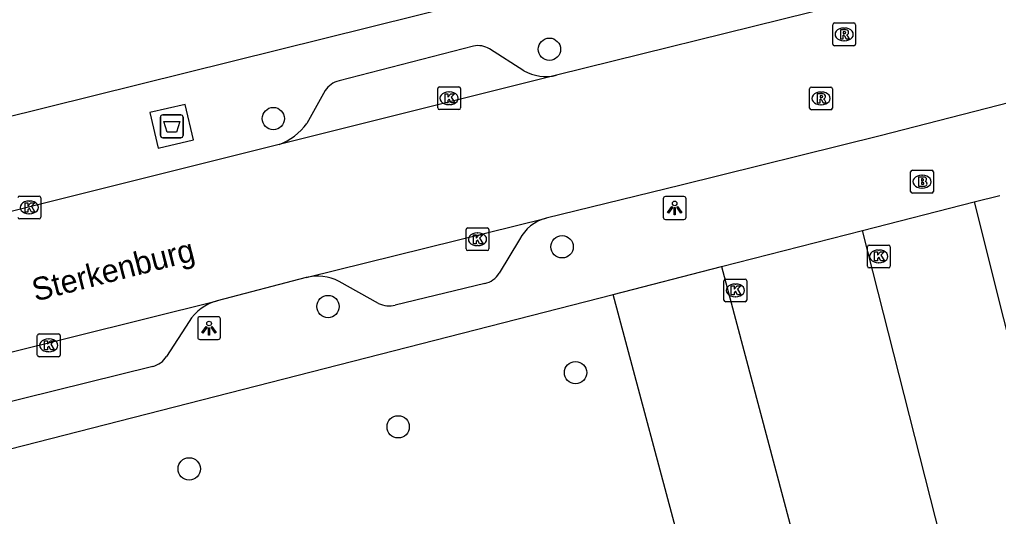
# Model space of a CAD drawing. Extents: x 157793 to 159380, y 380882 to 382313.
# Drawn here: x 158565.92 to 158608.83, y 381261.79 to 381283.58 of the extents above; entities that cross this region are included whole.
import ezdxf

# ---------------------------------------------------------------- set-up
doc = ezdxf.new("R2010")
doc.units = 0
for name, color, linetype in [('IMGEO_Afval_apart_plaats', 7, 'Continuous'), ('IMGEO_Boom', 7, 'Continuous'), ('IMGEO_Brandkraan', 7, 'Continuous'), ('IMGEO_Kolk', 7, 'Continuous'), ('IMGEO_Lichtpunt', 7, 'Continuous'), ('IMGEO_Openbare_ruimte_label', 7, 'Continuous'), ('IMGEO_Parkeervlak_open', 7, 'Continuous'), ('IMGEO_Rijbaan_lokaal_gesloten', 7, 'Continuous'), ('IMGEO_Rijbaan_lokaal_open', 7, 'Continuous'), ('IMGEO_Rioolput', 7, 'Continuous'), ('IMGEO_Voetpad_gesloten', 7, 'Continuous'), ('IMGEO_Voetpad_open', 7, 'Continuous')]:
    doc.layers.add(name, color=color, linetype=linetype)

msp = doc.modelspace()

# ---------------------------------------------------------------- linework, layer by layer
at = {"layer": 'IMGEO_Afval_apart_plaats'}
for p, q in [((158572.097, 381278.498), (158572.097, 381279.298)), ((158572.097, 381279.298), (158572.097, 381278.498)), ((158572.197, 381279.398), (158572.987, 381279.398)), ((158572.987, 381279.398), (158572.197, 381279.398)), ((158573.087, 381279.298), (158573.087, 381278.498)), ((158573.087, 381278.498), (158573.087, 381279.298)), ((158572.987, 381278.398), (158572.197, 381278.398)), ((158572.197, 381278.398), (158572.987, 381278.398))]:
    msp.add_line(p, q, dxfattribs=at)
msp.add_lwpolyline([(158572.24, 381279.112), (158572.944, 381279.112), (158572.795, 381278.642), (158572.389, 381278.642), (158572.24, 381279.112)], dxfattribs=at)
for centre, start, end in [((158572.197, 381279.298), 90, 180), ((158572.197, 381279.298), 90, 180), ((158572.987, 381279.298), 0, 90), ((158572.987, 381279.298), 360, 90), ((158572.197, 381278.498), 180, 270), ((158572.197, 381278.498), 180, 270), ((158572.987, 381278.498), 270, 0), ((158572.987, 381278.498), 270, 0)]:
    msp.add_arc(centre, 0.1, start, end, dxfattribs=at)
at = {"layer": 'IMGEO_Boom'}
for centre in [(158589.147, 381282.275), (158577.046, 381279.235), (158589.702, 381273.613), (158579.443, 381270.995), (158590.291, 381268.096), (158582.517, 381265.72), (158573.359, 381263.875)]:
    msp.add_circle(centre, 0.489, dxfattribs=at)
at = {"layer": 'IMGEO_Brandkraan'}
for p, q in [((158604.979, 381276.043), (158604.979, 381276.895)), ((158605.054, 381276.969), (158605.906, 381276.969)), ((158605.467, 381276.749), (158605.492, 381276.749)), ((158605.98, 381276.895), (158605.98, 381276.043)), ((158605.49, 381276.189), (158605.465, 381276.189)), ((158605.906, 381275.969), (158605.054, 381275.969))]:
    msp.add_line(p, q, dxfattribs=at)
for points in [[(158604.979, 381276.043), (158604.979, 381276.895)], [(158605.054, 381276.969), (158605.906, 381276.969)], [(158605.327, 381276.669), (158605.327, 381276.269), (158605.54, 381276.269)], [(158605.558, 381276.669), (158605.327, 381276.669)], [(158605.506, 381276.588), (158605.452, 381276.588), (158605.452, 381276.512)], [(158605.98, 381276.895), (158605.98, 381276.043)], [(158605.452, 381276.512), (158605.505, 381276.512)], [(158605.514, 381276.436), (158605.452, 381276.436), (158605.452, 381276.355)], [(158605.452, 381276.355), (158605.514, 381276.355)], [(158605.906, 381275.969), (158605.054, 381275.969)]]:
    msp.add_lwpolyline(points, dxfattribs=at)
for centre, radius, start, end in [((158605.056, 381276.893), 0.0765, 91.552, 178.448), ((158605.056, 381276.893), 0.0765, 91.552, 178.448), ((158605.507, 381276.55), 0.0379, 267.8285, 90.9355), ((158605.562, 381276.524), 0.145, 59.4692, 91.5367), ((158605.587, 381276.571), 0.0922, 285.5137, 58.1501), ((158605.904, 381276.893), 0.0765, 1.552, 88.448), ((158605.904, 381276.893), 0.0765, 1.552, 88.448), ((158605.515, 381276.395), 0.0404, 269.8759, 90.5077), ((158605.546, 381276.52), 0.251, 268.6676, 293.5347), ((158605.592, 381276.379), 0.105, 301.3115, 78.989), ((158605.056, 381276.045), 0.0765, 181.552, 268.448), ((158605.056, 381276.045), 0.0765, 181.552, 268.448), ((158605.904, 381276.045), 0.0765, 271.552, 358.448), ((158605.904, 381276.045), 0.0765, 271.552, 358.448)]:
    msp.add_arc(centre, radius, start, end, dxfattribs=at)
for centre, major_axis, ratio, start_param, end_param in [((158605.466, 381276.469), (-0.387, 0.002), 0.722429, 4.712389, 7.853982), ((158605.491, 381276.469), (-0.39, 0.002), 0.717154, 1.570796, 4.712389)]:
    msp.add_ellipse(centre, major_axis=major_axis, ratio=ratio, start_param=start_param, end_param=end_param, dxfattribs=at)
at = {"layer": 'IMGEO_Kolk'}
for p, q in [((158584.25, 381279.701), (158584.25, 381280.553)), ((158584.325, 381280.627), (158585.177, 381280.627)), ((158585.251, 381280.553), (158585.251, 381279.701)), ((158584.738, 381280.407), (158584.763, 381280.407)), ((158585.177, 381279.627), (158584.325, 381279.627)), ((158584.761, 381279.847), (158584.736, 381279.847)), ((158565.924, 381275.839), (158566.776, 381275.839)), ((158566.85, 381275.765), (158566.85, 381274.913)), ((158566.337, 381275.619), (158566.362, 381275.619)), ((158566.36, 381275.059), (158566.335, 381275.059)), ((158566.776, 381274.839), (158565.924, 381274.839)), ((158585.569, 381274.445), (158586.421, 381274.445)), ((158585.494, 381273.519), (158585.494, 381274.371)), ((158585.982, 381274.225), (158586.007, 381274.225)), ((158586.495, 381274.371), (158586.495, 381273.519)), ((158586.005, 381273.665), (158585.98, 381273.665)), ((158603.081, 381272.765), (158603.081, 381273.617)), ((158603.156, 381273.691), (158604.008, 381273.691)), ((158604.082, 381273.617), (158604.082, 381272.765)), ((158586.421, 381273.445), (158585.569, 381273.445)), ((158603.569, 381273.471), (158603.594, 381273.471)), ((158603.592, 381272.911), (158603.567, 381272.911)), ((158604.008, 381272.691), (158603.156, 381272.691)), ((158596.797, 381271.275), (158596.797, 381272.127)), ((158596.872, 381272.201), (158597.724, 381272.201)), ((158597.285, 381271.981), (158597.31, 381271.981)), ((158597.798, 381272.127), (158597.798, 381271.275)), ((158597.308, 381271.421), (158597.283, 381271.421)), ((158597.724, 381271.201), (158596.872, 381271.201)), ((158566.702, 381268.869), (158566.702, 381269.721)), ((158566.777, 381269.795), (158567.629, 381269.795)), ((158567.703, 381269.721), (158567.703, 381268.869)), ((158567.19, 381269.575), (158567.215, 381269.575)), ((158567.213, 381269.015), (158567.188, 381269.015)), ((158567.629, 381268.795), (158566.777, 381268.795))]:
    msp.add_line(p, q, dxfattribs=at)
for points in [[(158584.25, 381279.701), (158584.25, 381280.553)], [(158584.325, 381280.627), (158585.177, 381280.627)], [(158585.251, 381280.553), (158585.251, 381279.701)], [(158584.571, 381280.327), (158584.694, 381280.327), (158584.694, 381280.176), (158584.824, 381280.327), (158584.988, 381280.327), (158584.842, 381280.176), (158584.995, 381279.927), (158584.843, 381279.927), (158584.758, 381280.091), (158584.694, 381280.024), (158584.694, 381279.927), (158584.571, 381279.927), (158584.571, 381280.327)], [(158585.177, 381279.627), (158584.325, 381279.627)], [(158565.924, 381275.839), (158566.776, 381275.839)], [(158566.85, 381275.765), (158566.85, 381274.913)], [(158566.17, 381275.539), (158566.293, 381275.539), (158566.293, 381275.388), (158566.423, 381275.539), (158566.587, 381275.539), (158566.441, 381275.388), (158566.594, 381275.139), (158566.442, 381275.139), (158566.357, 381275.303), (158566.293, 381275.236), (158566.293, 381275.139), (158566.17, 381275.139), (158566.17, 381275.539)], [(158566.776, 381274.839), (158565.924, 381274.839)], [(158585.569, 381274.445), (158586.421, 381274.445)], [(158585.494, 381273.519), (158585.494, 381274.371)], [(158585.815, 381274.145), (158585.938, 381274.145), (158585.938, 381273.994), (158586.068, 381274.145), (158586.232, 381274.145), (158586.086, 381273.994), (158586.239, 381273.745), (158586.087, 381273.745), (158586.002, 381273.909), (158585.938, 381273.842), (158585.938, 381273.745), (158585.815, 381273.745), (158585.815, 381274.145)], [(158586.495, 381274.371), (158586.495, 381273.519)], [(158603.081, 381272.765), (158603.081, 381273.617)], [(158603.156, 381273.691), (158604.008, 381273.691)], [(158604.082, 381273.617), (158604.082, 381272.765)], [(158586.421, 381273.445), (158585.569, 381273.445)], [(158603.402, 381273.391), (158603.525, 381273.391), (158603.525, 381273.24), (158603.655, 381273.391), (158603.819, 381273.391), (158603.673, 381273.24), (158603.826, 381272.991), (158603.674, 381272.991), (158603.589, 381273.155), (158603.525, 381273.088), (158603.525, 381272.991), (158603.402, 381272.991), (158603.402, 381273.391)], [(158604.008, 381272.691), (158603.156, 381272.691)], [(158596.797, 381271.275), (158596.797, 381272.127)], [(158596.872, 381272.201), (158597.724, 381272.201)], [(158597.118, 381271.901), (158597.241, 381271.901), (158597.241, 381271.75), (158597.371, 381271.901), (158597.535, 381271.901), (158597.389, 381271.75), (158597.542, 381271.501), (158597.39, 381271.501), (158597.305, 381271.665), (158597.241, 381271.598), (158597.241, 381271.501), (158597.118, 381271.501), (158597.118, 381271.901)], [(158597.798, 381272.127), (158597.798, 381271.275)], [(158597.724, 381271.201), (158596.872, 381271.201)], [(158566.702, 381268.869), (158566.702, 381269.721)], [(158566.777, 381269.795), (158567.629, 381269.795)], [(158567.703, 381269.721), (158567.703, 381268.869)], [(158567.023, 381269.495), (158567.146, 381269.495), (158567.146, 381269.344), (158567.276, 381269.495), (158567.44, 381269.495), (158567.294, 381269.344), (158567.447, 381269.095), (158567.295, 381269.095), (158567.21, 381269.259), (158567.146, 381269.192), (158567.146, 381269.095), (158567.023, 381269.095), (158567.023, 381269.495)], [(158567.629, 381268.795), (158566.777, 381268.795)]]:
    msp.add_lwpolyline(points, dxfattribs=at)
for centre, start, end in [((158584.327, 381280.551), 91.552, 178.448), ((158584.327, 381280.551), 91.552, 178.448), ((158585.175, 381280.551), 1.552, 88.448), ((158585.175, 381280.551), 1.552, 88.448), ((158584.327, 381279.703), 181.552, 268.448), ((158584.327, 381279.703), 181.552, 268.448), ((158585.175, 381279.703), 271.552, 358.448), ((158585.175, 381279.703), 271.552, 358.448), ((158565.926, 381275.763), 91.552, 178.448), ((158565.926, 381275.763), 91.552, 178.448), ((158566.774, 381275.763), 1.552, 88.448), ((158566.774, 381275.763), 1.552, 88.448), ((158565.926, 381274.915), 181.552, 268.448), ((158565.926, 381274.915), 181.552, 268.448), ((158566.774, 381274.915), 271.552, 358.448), ((158566.774, 381274.915), 271.552, 358.448), ((158585.571, 381274.369), 91.552, 178.448), ((158585.571, 381274.369), 91.552, 178.448), ((158586.419, 381274.369), 1.552, 88.448), ((158586.419, 381274.369), 1.552, 88.448), ((158603.158, 381273.615), 91.552, 178.448), ((158603.158, 381273.615), 91.552, 178.448), ((158604.006, 381273.615), 1.552, 88.448), ((158604.006, 381273.615), 1.552, 88.448), ((158585.571, 381273.521), 181.552, 268.448), ((158585.571, 381273.521), 181.552, 268.448), ((158586.419, 381273.521), 271.552, 358.448), ((158586.419, 381273.521), 271.552, 358.448), ((158603.158, 381272.767), 181.552, 268.448), ((158603.158, 381272.767), 181.552, 268.448), ((158604.006, 381272.767), 271.552, 358.448), ((158604.006, 381272.767), 271.552, 358.448), ((158596.874, 381272.125), 91.552, 178.448), ((158596.874, 381272.125), 91.552, 178.448), ((158597.722, 381272.125), 1.552, 88.448), ((158597.722, 381272.125), 1.552, 88.448), ((158596.874, 381271.277), 181.552, 268.448), ((158596.874, 381271.277), 181.552, 268.448), ((158597.722, 381271.277), 271.552, 358.448), ((158597.722, 381271.277), 271.552, 358.448), ((158566.779, 381269.719), 91.552, 178.448), ((158566.779, 381269.719), 91.552, 178.448), ((158567.627, 381269.719), 1.552, 88.448), ((158567.627, 381269.719), 1.552, 88.448), ((158566.779, 381268.871), 181.552, 268.448), ((158566.779, 381268.871), 181.552, 268.448), ((158567.627, 381268.871), 271.552, 358.448), ((158567.627, 381268.871), 271.552, 358.448)]:
    msp.add_arc(centre, 0.0765, start, end, dxfattribs=at)
for centre, major_axis, ratio, start_param, end_param in [((158584.737, 381280.127), (-0.387, 0.002), 0.722429, 4.712389, 7.853982), ((158584.762, 381280.127), (-0.39, 0.002), 0.717154, 1.570796, 4.712389), ((158566.336, 381275.339), (-0.387, 0.002), 0.722429, 4.712389, 7.853982), ((158566.361, 381275.339), (-0.39, 0.002), 0.717154, 1.570796, 4.712389), ((158585.981, 381273.945), (-0.387, 0.002), 0.722429, 4.712389, 7.853982), ((158586.006, 381273.945), (-0.39, 0.002), 0.717154, 1.570796, 4.712389), ((158603.568, 381273.191), (-0.387, 0.002), 0.722429, 4.712389, 7.853982), ((158603.593, 381273.191), (-0.39, 0.002), 0.717154, 1.570796, 4.712389), ((158597.284, 381271.701), (-0.387, 0.002), 0.722429, 4.712389, 7.853982), ((158597.309, 381271.701), (-0.39, 0.002), 0.717154, 1.570796, 4.712389), ((158567.189, 381269.295), (-0.387, 0.002), 0.722429, 4.712389, 7.853982), ((158567.214, 381269.295), (-0.39, 0.002), 0.717154, 1.570796, 4.712389)]:
    msp.add_ellipse(centre, major_axis=major_axis, ratio=ratio, start_param=start_param, end_param=end_param, dxfattribs=at)
at = {"layer": 'IMGEO_Lichtpunt'}
for p, q in [((158594.139, 381275.718), (158594.139, 381274.911)), ((158594.139, 381275.718), (158594.139, 381274.911)), ((158595.041, 381275.813), (158594.233, 381275.813)), ((158595.041, 381275.813), (158594.233, 381275.813)), ((158595.135, 381274.911), (158595.135, 381275.718)), ((158595.135, 381274.911), (158595.135, 381275.718)), ((158594.233, 381274.817), (158595.041, 381274.817)), ((158594.233, 381274.817), (158595.041, 381274.817)), ((158573.731, 381270.451), (158573.731, 381269.644)), ((158573.731, 381270.451), (158573.731, 381269.644)), ((158574.633, 381270.546), (158573.825, 381270.546)), ((158574.633, 381270.546), (158573.825, 381270.546)), ((158574.727, 381269.644), (158574.727, 381270.451)), ((158574.727, 381269.644), (158574.727, 381270.451)), ((158573.825, 381269.55), (158574.633, 381269.55)), ((158573.825, 381269.55), (158574.633, 381269.55))]:
    msp.add_line(p, q, dxfattribs=at)
for points in [[(158594.513, 381275.382), (158594.552, 381275.354), (158594.364, 381275.092), (158594.326, 381275.119), (158594.513, 381275.382)], [(158594.615, 381275.334), (158594.662, 381275.334), (158594.662, 381275.012), (158594.615, 381275.012), (158594.615, 381275.334)], [(158594.725, 381275.354), (158594.763, 381275.381), (158594.95, 381275.119), (158594.911, 381275.091), (158594.725, 381275.354)], [(158574.105, 381270.115), (158574.144, 381270.087), (158573.956, 381269.825), (158573.918, 381269.852), (158574.105, 381270.115)], [(158574.207, 381270.067), (158574.254, 381270.067), (158574.254, 381269.745), (158574.207, 381269.745), (158574.207, 381270.067)], [(158574.317, 381270.087), (158574.355, 381270.114), (158574.542, 381269.852), (158574.503, 381269.824), (158574.317, 381270.087)]]:
    msp.add_lwpolyline(points, dxfattribs=at)
for centre in [(158594.638, 381275.516), (158574.23, 381270.249)]:
    msp.add_circle(centre, 0.0994, dxfattribs=at)
for centre, start, end in [((158594.233, 381275.718), 90, 180), ((158594.233, 381275.718), 90, 180), ((158595.041, 381275.718), 0, 90), ((158595.041, 381275.718), 0, 90), ((158594.233, 381274.911), 180, 270), ((158594.233, 381274.911), 180, 270), ((158595.041, 381274.911), 270, 0), ((158595.041, 381274.911), 270, 360), ((158573.825, 381270.451), 90, 180), ((158573.825, 381270.451), 90, 180), ((158574.633, 381270.451), 0, 90), ((158574.633, 381270.451), 0, 90), ((158573.825, 381269.644), 180, 270), ((158573.825, 381269.644), 180, 270), ((158574.633, 381269.644), 270, 0), ((158574.633, 381269.644), 270, 360)]:
    msp.add_arc(centre, 0.0946, start, end, dxfattribs=at)
at = {"layer": 'IMGEO_Parkeervlak_open'}
msp.add_lwpolyline([(158595.165, 381259.444), (158591.941, 381271.524)], dxfattribs=at)
at = {"layer": 'IMGEO_Rijbaan_lokaal_gesloten'}
for points in [[(158609.469, 381286.151), (158607.008, 381285.513), (158600.58, 381283.887), (158589.462, 381281.136)], [(158589.462, 381281.136), (158577.301, 381278.092)], [(158610.86, 381280.329), (158603.643, 381278.485), (158594.916, 381276.32), (158588.997, 381274.872)], [(158577.301, 381278.092), (158564.14, 381274.813), (158563.943, 381274.765)], [(158578.484, 381272.266), (158588.997, 381274.872)], [(158578.484, 381272.266), (158574.577, 381271.247)], [(158552.613, 381265.784), (158574.577, 381271.247)]]:
    msp.add_lwpolyline(points, dxfattribs=at)
at = {"layer": 'IMGEO_Rijbaan_lokaal_open'}
for points in [[(158596.695, 381272.743), (158602.868, 381274.325)], [(158612.762, 381235.389), (158609.049, 381250), (158602.868, 381274.325)], [(158596.695, 381272.743), (158602.738, 381250), (158608.211, 381229.407), (158605.839, 381228.792), (158607.018, 381224.243), (158604.549, 381223.603)]]:
    msp.add_lwpolyline(points, dxfattribs=at)
at = {"layer": 'IMGEO_Rioolput'}
for p, q in [((158601.639, 381283.427), (158602.491, 381283.427)), ((158601.564, 381282.501), (158601.564, 381283.353)), ((158602.052, 381283.207), (158602.077, 381283.207)), ((158602.565, 381283.353), (158602.565, 381282.501)), ((158602.075, 381282.647), (158602.05, 381282.647)), ((158602.491, 381282.427), (158601.639, 381282.427)), ((158600.552, 381279.693), (158600.552, 381280.545)), ((158600.627, 381280.619), (158601.479, 381280.619)), ((158601.553, 381280.545), (158601.553, 381279.693)), ((158601.04, 381280.399), (158601.065, 381280.399)), ((158601.479, 381279.619), (158600.627, 381279.619)), ((158601.063, 381279.839), (158601.038, 381279.839))]:
    msp.add_line(p, q, dxfattribs=at)
for points in [[(158601.639, 381283.427), (158602.491, 381283.427)], [(158601.564, 381282.501), (158601.564, 381283.353)], [(158602.153, 381283.125), (158601.901, 381283.127), (158601.901, 381282.727)], [(158602.079, 381283.046), (158602.025, 381283.046), (158602.025, 381282.965)], [(158602.565, 381283.353), (158602.565, 381282.501)], [(158601.901, 381282.727), (158602.025, 381282.727), (158602.025, 381282.889), (158602.036, 381282.889)], [(158602.025, 381282.965), (158602.077, 381282.965)], [(158602.083, 381282.86), (158602.154, 381282.727), (158602.294, 381282.727), (158602.229, 381282.853)], [(158602.491, 381282.427), (158601.639, 381282.427)], [(158600.552, 381279.693), (158600.552, 381280.545)], [(158600.627, 381280.619), (158601.479, 381280.619)], [(158601.553, 381280.545), (158601.553, 381279.693)], [(158601.141, 381280.317), (158600.889, 381280.319), (158600.889, 381279.919)], [(158600.889, 381279.919), (158601.013, 381279.919), (158601.013, 381280.081), (158601.024, 381280.081)], [(158601.067, 381280.238), (158601.013, 381280.238), (158601.013, 381280.157)], [(158601.013, 381280.157), (158601.065, 381280.157)], [(158601.071, 381280.052), (158601.142, 381279.919), (158601.282, 381279.919), (158601.217, 381280.045)], [(158601.479, 381279.619), (158600.627, 381279.619)]]:
    msp.add_lwpolyline(points, dxfattribs=at)
for centre, radius, start, end in [((158601.641, 381283.351), 0.0765, 91.552, 178.448), ((158601.641, 381283.351), 0.0765, 91.552, 178.448), ((158602.489, 381283.351), 0.0765, 1.552, 88.448), ((158602.489, 381283.351), 0.0765, 1.552, 88.448), ((158602.085, 381282.95), 0.0964, 77.0061, 93.1865), ((158602.099, 381283.007), 0.0378, 276.6634, 79.6772), ((158602.152, 381283.015), 0.109, 350.3612, 89.416), ((158602.15, 381283.015), 0.112, 277.5842, 350.9817), ((158602.035, 381282.836), 0.0533, 26.0293, 88.6989), ((158602.061, 381283.154), 0.19, 274.7715, 282.9687), ((158602.134, 381282.8), 0.108, 29.5134, 73.7905), ((158601.641, 381282.503), 0.0765, 181.552, 268.448), ((158601.641, 381282.503), 0.0765, 181.552, 268.448), ((158602.489, 381282.503), 0.0765, 271.552, 358.448), ((158602.489, 381282.503), 0.0765, 271.552, 358.448), ((158600.629, 381280.543), 0.0765, 91.552, 178.448), ((158600.629, 381280.543), 0.0765, 91.552, 178.448), ((158601.477, 381280.543), 0.0765, 1.552, 88.448), ((158601.477, 381280.543), 0.0765, 1.552, 88.448), ((158601.023, 381280.028), 0.0533, 26.0293, 88.6989), ((158601.049, 381280.346), 0.19, 274.7715, 282.9687), ((158601.073, 381280.142), 0.0964, 77.0061, 93.1865), ((158601.087, 381280.199), 0.0378, 276.6634, 79.6772), ((158601.14, 381280.207), 0.109, 350.3612, 89.416), ((158601.138, 381280.207), 0.112, 277.5842, 350.9817), ((158601.122, 381279.992), 0.108, 29.5134, 73.7905), ((158600.629, 381279.695), 0.0765, 181.552, 268.448), ((158600.629, 381279.695), 0.0765, 181.552, 268.448), ((158601.477, 381279.695), 0.0765, 271.552, 358.448), ((158601.477, 381279.695), 0.0765, 271.552, 358.448)]:
    msp.add_arc(centre, radius, start, end, dxfattribs=at)
for centre, major_axis, ratio, start_param, end_param in [((158602.051, 381282.927), (-0.387, 0.002), 0.722429, 4.712389, 7.853982), ((158602.076, 381282.927), (-0.39, 0.002), 0.717154, 1.570796, 4.712389), ((158601.039, 381280.119), (-0.387, 0.002), 0.722429, 4.712389, 7.853982), ((158601.064, 381280.119), (-0.39, 0.002), 0.717154, 1.570796, 4.712389)]:
    msp.add_ellipse(centre, major_axis=major_axis, ratio=ratio, start_param=start_param, end_param=end_param, dxfattribs=at)
at = {"layer": 'IMGEO_Voetpad_gesloten'}
msp.add_lwpolyline([(158573.187, 381279.854), (158571.639, 381279.498), (158571.997, 381277.942), (158573.545, 381278.298), (158573.187, 381279.854)], dxfattribs=at)
at = {"layer": 'IMGEO_Voetpad_open'}
for points in [[(158599.553, 381287.79), (158542.795, 381273.686), (158537.268, 381272.476)], [(158585.822, 381282.413), (158579.926, 381280.896)], [(158588.023, 381281.333), (158586.519, 381282.292)], [(158579.316, 381280.461), (158578.509, 381279.023)], [(158607.76, 381275.579), (158608.885, 381275.867)], [(158602.868, 381274.325), (158607.76, 381275.579)], [(158607.76, 381275.579), (158614.181, 381250), (158616.889, 381239.212), (158615.264, 381238.824), (158614.977, 381238.734), (158614.698, 381238.619), (158614.431, 381238.479), (158614.178, 381238.316), (158613.94, 381238.131), (158613.72, 381237.926), (158613.519, 381237.701), (158613.339, 381237.46), (158613.181, 381237.204), (158613.047, 381236.934), (158612.937, 381236.654), (158612.853, 381236.364), (158612.795, 381236.069), (158612.763, 381235.769), (158612.759, 381235.468), (158612.762, 381235.389)], [(158587.84, 381273.937), (158586.938, 381272.456)], [(158591.941, 381271.524), (158596.695, 381272.743)], [(158581.662, 381271.133), (158579.926, 381272.098)], [(158586.311, 381272.007), (158582.393, 381271.058)], [(158559.097, 381263), (158559.462, 381263.2), (158591.941, 381271.524)], [(158573.351, 381270.339), (158572.367, 381268.804)], [(158571.76, 381268.37), (158556.05, 381264.479)]]:
    msp.add_lwpolyline(points, dxfattribs=at)
for centre, radius, start, end in [((158586.02, 381281.486), 0.948, 58.2397, 102.0634), ((158588.993, 381283.063), 1.983, 240.7241, 283.6852), ((158580.177, 381279.898), 1.029, 104.1412, 146.8452), ((158576.389, 381280.525), 2.598, 290.5557, 324.6869), ((158589.465, 381273.11), 1.823, 104.8691, 153.016), ((158578.978, 381270.232), 2.094, 63.0674, 103.6421), ((158586.133, 381272.918), 0.928, 281.0472, 330.1663), ((158575.145, 381269.199), 2.125, 105.4916, 147.5571), ((158582.13, 381272.099), 1.074, 244.1297, 284.1543), ((158571.545, 381269.312), 0.966, 282.8554, 328.2736)]:
    msp.add_arc(centre, radius, start, end, dxfattribs=at)

# ---------------------------------------------------------------- texts
at = {"layer": 'IMGEO_Openbare_ruimte_label'}
msp.add_text('Sterkenburg', height=1, rotation=14.4113, dxfattribs=at).set_placement((158566.617, 381271.211))

doc.saveas('drawing.dxf')
